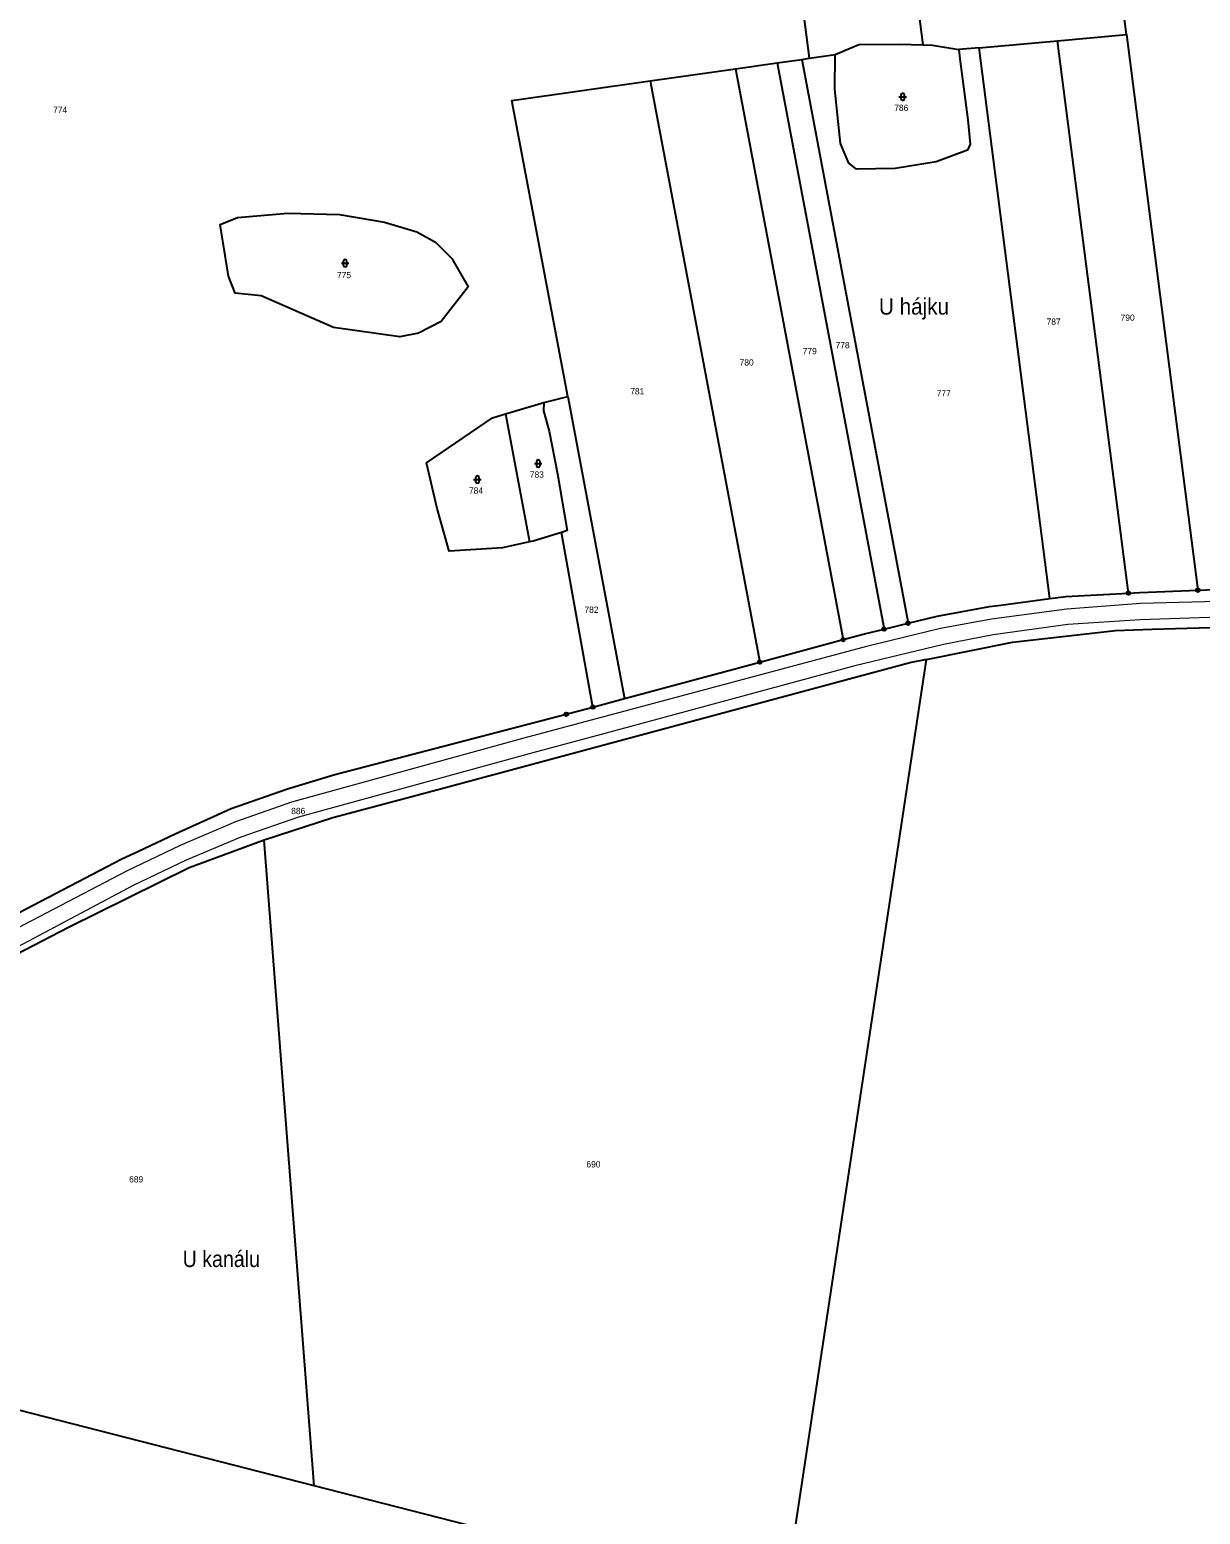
# Model space of a CAD drawing. Extents: x -754445 to -751443, y -1030748 to -1028224.
# Drawn here: x -752041.3 to -751724.9, y -1029290.6 to -1028889.3 of the extents above; entities that cross this region are included whole.
import ezdxf
from ezdxf.enums import TextEntityAlignment as Align

# ---------------------------------------------------------------- set-up
doc = ezdxf.new("R2010")
doc.units = 0
doc.header["$LTSCALE"] = 0.68
for name, color, linetype, lineweight in [('1', 7, 'Continuous', 25), ('3', 7, 'Continuous', 25), ('4', 7, 'Continuous', 13), ('7', 7, 'Continuous', 13), ('8', 7, 'Continuous', 25)]:
    doc.layers.add(name, color=color, linetype=linetype, lineweight=lineweight)
doc.layers.add('2', color=7, linetype='Continuous')

msp = doc.modelspace()

# ---------------------------------------------------------------- linework, layer by layer
at = {"layer": '1'}
for p, q in [((-751744.3, -1029041.58), (-751763.49, -1028892.26)), ((-751744.86, -1028890.61), (-751725.55, -1029040.8)), ((-751830.47, -1028896.99), (-751823.58, -1028896.01)), ((-751784.69, -1028894.13), (-751790.16, -1028894.61)), ((-751850.52, -1028899.83), (-751821.41, -1029054.15)), ((-751832.61, -1028897.29), (-751803.86, -1029049.73)), ((-751895.86, -1028988.44), (-751880.47, -1029070.06)), ((-751912.68, -1028993.15), (-751906.16, -1029027.72)), ((-751737.86, -1029051.34), (-751662.37, -1029049.03)), ((-751880.47, -1029070.06), (-751843.94, -1029060.22)), ((-751889.04, -1029072.37), (-751880.47, -1029070.06)), ((-751964.38, -1029282.9), (-751977.87, -1029108.32)), ((-751964.38, -1029282.9), (-752047.7, -1029261.57))]:
    msp.add_line(p, q, dxfattribs=at)
for points in [[(-751744.86, -1028890.61), (-751763.8, -1028743.25), (-751782.74, -1028595.88)], [(-751799.79, -1028893.34), (-751818.35, -1028749.15), (-751836.91, -1028604.96)], [(-751830.47, -1028896.99), (-751849.02, -1028752.71), (-751867.56, -1028608.43)], [(-751784.69, -1028894.13), (-751763.49, -1028892.26), (-751744.86, -1028890.61)], [(-751790.16, -1028894.61), (-751789.86, -1028897.18), (-751787.75, -1028913.66), (-751787.04, -1028920.21), (-751787.84, -1028921.81), (-751796.31, -1028924.97), (-751807.34, -1028926.8), (-751817.83, -1028926.98), (-751819.91, -1028925.32), (-751822.09, -1028920), (-751823.64, -1028905.31), (-751823.58, -1028896.01)], [(-751823.58, -1028896.01), (-751817.14, -1028893.26), (-751806.24, -1028893.15), (-751799.79, -1028893.34)], [(-751803.86, -1029049.73), (-751796.03, -1029047.82), (-751781.83, -1029045.2), (-751778.76, -1029044.83), (-751765.55, -1029043.04), (-751784.69, -1028894.13)], [(-751799.79, -1028893.34), (-751797.28, -1028893.42), (-751790.16, -1028894.61)], [(-751873.57, -1028903.1), (-751850.52, -1028899.83), (-751839.23, -1028898.23), (-751832.61, -1028897.29), (-751830.47, -1028896.99)], [(-751839.23, -1028898.23), (-751810.36, -1029051.31), (-751803.86, -1029049.73)], [(-751895.86, -1028988.44), (-751910.96, -1028908.4), (-751873.57, -1028903.1)], [(-751873.57, -1028903.1), (-751843.94, -1029060.22), (-751821.41, -1029054.15)], [(-751906.16, -1029027.72), (-751913.49, -1029029.3), (-751927.87, -1029030.2), (-751931.13, -1029018.69), (-751934.06, -1029006.31), (-751916.14, -1028994.18), (-751912.68, -1028993.15), (-751902.34, -1028990.08), (-751895.86, -1028988.44)], [(-751902.34, -1028990.08), (-751902.43, -1028992.32), (-751900.83, -1028997.79), (-751898.63, -1029009.34), (-751895.96, -1029024.67), (-751897.56, -1029025.16)], [(-752269.77, -1029223.33), (-752267.32, -1029222.61), (-752255.58, -1029222.51), (-752238.99, -1029219.81), (-752224.7, -1029216.51), (-752209.16, -1029211.98), (-752199.81, -1029208.36), (-752186.4, -1029202.26), (-752154.19, -1029185), (-752151.32, -1029183.38), (-752097.6, -1029156.03), (-752093.86, -1029154.17), (-752058.37, -1029135.25), (-752016.36, -1029113.42), (-752011.99, -1029111.42), (-752001.98, -1029106.62), (-751986.78, -1029099.78), (-751971.62, -1029094.47), (-751958.78, -1029090.62), (-751896.26, -1029074.31), (-751889.04, -1029072.37), (-751897.56, -1029025.16)], [(-751897.56, -1029025.16), (-751905.21, -1029027.51), (-751906.16, -1029027.72)], [(-751744.3, -1029041.58), (-751741.24, -1029041.42), (-751725.55, -1029040.8)], [(-751725.55, -1029040.8), (-751692.53, -1029039.49), (-751671.43, -1029039.02)], [(-751765.55, -1029043.04), (-751761.18, -1029042.45), (-751744.3, -1029041.58)], [(-751821.41, -1029054.15), (-751815.68, -1029052.61), (-751810.36, -1029051.31)], [(-751798.91, -1029059.52), (-751775.67, -1029054.81), (-751747.77, -1029051.64), (-751737.86, -1029051.34)], [(-751798.91, -1029059.52), (-751803.05, -1029060.36), (-751932.61, -1029095.24), (-751959.35, -1029102.28), (-751977.87, -1029108.32)], [(-751832.21, -1029280.14), (-751815.56, -1029169.83), (-751798.91, -1029059.52)], [(-751977.87, -1029108.32), (-751998.14, -1029115.79), (-752030.8, -1029131.95), (-752066.25, -1029150.34)], [(-751911.37, -1029420.62), (-751856.24, -1029439.29), (-751832.21, -1029280.14)], [(-751911.37, -1029420.62), (-751893.33, -1029301.09), (-751964.38, -1029282.9)]]:
    msp.add_lwpolyline(points, dxfattribs=at)
msp.add_lwpolyline([(-751985.1, -1028940.02), (-751971.52, -1028938.83), (-751957.51, -1028939.22), (-751945.35, -1028941.32), (-751936.65, -1028943.94), (-751931.59, -1028946.73), (-751927.21, -1028951.13), (-751922.8, -1028958.8), (-751930.04, -1028968.13), (-751936.15, -1028971.3), (-751941.21, -1028972.29), (-751959.11, -1028969.76), (-751978.72, -1028961.22), (-751985.75, -1028960.51), (-751987.52, -1028955.86), (-751989.74, -1028941.94)], close=True, dxfattribs=at)
at = {"layer": '3'}
for p, q in [((-751806.331, -1028907.421), (-751804.329, -1028907.421)), ((-751805.831, -1028906.921), (-751805.831, -1028907.922)), ((-751804.829, -1028907.922), (-751804.829, -1028906.921)), ((-751957.021, -1028952.401), (-751955.019, -1028952.401)), ((-751956.521, -1028951.901), (-751956.521, -1028952.902)), ((-751955.519, -1028952.902), (-751955.519, -1028951.901)), ((-751904.831, -1029006.551), (-751902.829, -1029006.551)), ((-751904.331, -1029006.051), (-751904.331, -1029007.052)), ((-751903.329, -1029007.052), (-751903.329, -1029006.051)), ((-751921.271, -1029010.891), (-751919.269, -1029010.891)), ((-751920.771, -1029010.391), (-751920.771, -1029011.392)), ((-751919.769, -1029011.392), (-751919.769, -1029010.391))]:
    msp.add_line(p, q, dxfattribs=at)
for centre, start, end in [((-751805.33, -1028906.9209), 0, 180), ((-751805.33, -1028907.9209), 180, 359.98789), ((-751956.02, -1028951.9009), 0, 180), ((-751956.02, -1028952.9009), 180, 359.98789), ((-751903.83, -1029006.0509), 0, 180), ((-751903.83, -1029007.0509), 180, 359.98789), ((-751920.27, -1029010.3909), 0, 180), ((-751920.27, -1029011.3909), 180, 359.98789)]:
    msp.add_arc(centre, 0.5, start, end, dxfattribs=at)
at = {"layer": '4'}
for points in [[(-751663.17, -1029043.04), (-751669, -1029042.93), (-751692.58, -1029043.16), (-751695.85, -1029043.21), (-751741.08, -1029044.36), (-751760.97, -1029045.91), (-751781.34, -1029048.64), (-751795.08, -1029051.13), (-751815.09, -1029055.96), (-751907.69, -1029080.76), (-751970.49, -1029098.06), (-751985.61, -1029103.42), (-752000.63, -1029109.83), (-752015.1, -1029116.71), (-752056.56, -1029138.39)], [(-751662.43, -1029047.11), (-751669.15, -1029047.09), (-751709.18, -1029047.75), (-751741.11, -1029048.78), (-751760.64, -1029050.09), (-751780.88, -1029052.82), (-751794.3, -1029055.49), (-751818.28, -1029061.21), (-751886.78, -1029079.83), (-751905.25, -1029084.72), (-751968.61, -1029102.14), (-751984.21, -1029107.52), (-751998.96, -1029113.8), (-752013.26, -1029120.59), (-752054.39, -1029142.39)]]:
    msp.add_lwpolyline(points, dxfattribs=at)
at = {"layer": '8'}
for centre, radius in [((-751744.3, -1029041.5799), 0.5), ((-751725.55, -1029040.7999), 0.5), ((-751725.55, -1029040.7999), 0.0303), ((-751744.3, -1029041.5799), 0.0303), ((-751810.36, -1029051.3099), 0.5), ((-751810.36, -1029051.3099), 0.0303), ((-751803.86, -1029049.7299), 0.5), ((-751803.86, -1029049.7299), 0.0303), ((-751821.41, -1029054.1499), 0.5), ((-751821.41, -1029054.1499), 0.0303), ((-751843.94, -1029060.2199), 0.5), ((-751843.94, -1029060.2199), 0.0303), ((-751889.04, -1029072.3699), 0.5), ((-751889.04, -1029072.3699), 0.0303), ((-751896.26, -1029074.3099), 0.5), ((-751896.26, -1029074.3099), 0.0303)]:
    msp.add_circle(centre, radius, dxfattribs=at)

# ---------------------------------------------------------------- texts
at = {"layer": '2'}
for s, p in [('774', (-752033.039, -1028911.786)), ('786', (-751805.699, -1028911.236)), ('775', (-751956.309, -1028956.436)), ('787', (-751764.519, -1028969.036)), ('790', (-751744.519, -1028967.966)), ('779', (-751830.439, -1028976.996)), ('778', (-751821.549, -1028975.386)), ('780', (-751847.489, -1028980.056)), ('781', (-751877.049, -1028987.866)), ('777', (-751794.219, -1028988.416)), ('783', (-751904.199, -1029010.366)), ('784', (-751920.639, -1029014.706)), ('782', (-751889.429, -1029046.906)), ('886', (-751968.679, -1029101.316)), ('690', (-751888.899, -1029196.82)), ('689', (-752012.479, -1029200.88))]:
    msp.add_text(s, height=1.7, dxfattribs=at).set_placement(p, align=Align.CENTER)
at = {"layer": '7', "width": 0.95}
msp.add_text('U hájku', height=4.4, dxfattribs=at).set_placement((-751811.74, -1028966.29))
at = {"layer": '7', "width": 0.9}
msp.add_text('U kanálu', height=4.4, dxfattribs=at).set_placement((-751989.469, -1029223.75), align=Align.CENTER)

doc.saveas('drawing.dxf')
